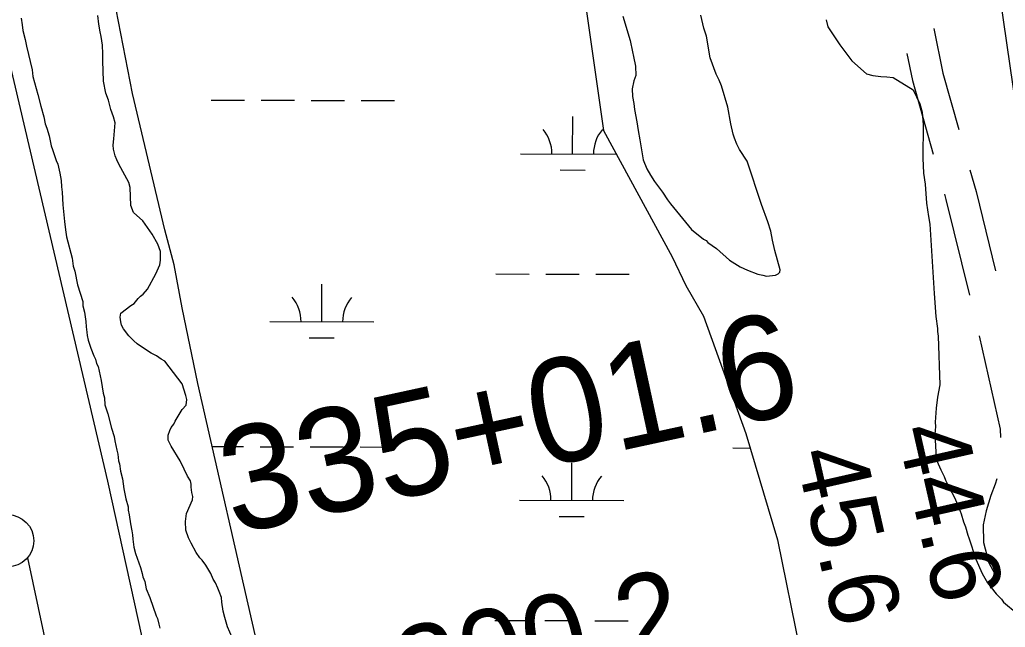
# Model space of a CAD drawing. Extents: x 3161665 to 3199565, y 885729 to 911164.
# Drawn here: x 3175026 to 3175972, y 895397 to 895980 of the extents above; entities that cross this region are included whole.
import ezdxf

# ---------------------------------------------------------------- set-up
doc = ezdxf.new("R2010")
doc.units = 0
for name, color, linetype in [('V-LEVE-TOET', 7, 'Continuous'), ('V-RIVR-RANG', 7, 'Continuous'), ('V-RIVR-RANG-IDEN', 7, 'Continuous'), ('V-ROAD-CNTR', 7, 'Continuous'), ('V-SITE-VEGE', 7, 'Continuous'), ('V-SURV-IDEN', 7, 'Continuous'), ('V-SURV-LINE', 7, 'Continuous'), ('V-TOPO-MINR', 7, 'Continuous'), ('V-TOPO-SHOR', 7, 'Continuous'), ('V-WETL-SWMP', 7, 'Continuous')]:
    doc.layers.add(name, color=color, linetype=linetype)

msp = doc.modelspace()

# ---------------------------------------------------------------- linework, layer by layer
at = {"layer": 'V-LEVE-TOET'}
msp.add_lwpolyline([(3174566.85, 897865.68), (3174635.83, 897583.71), (3174711.7, 897283.5), (3174795.82, 896920.93), (3174863.72, 896619.04), (3174934.5, 896318.62), (3175016.53, 895935.58), (3175109.93, 895536.94), (3175193.43, 895157.19), (3175269.57, 894793.2), (3175363, 894393.76), (3175446.73, 894021.24), (3175510.4, 893698.81), (3175596.82, 893326.15), (3175626.84, 893204.92), (3175671.16, 893055.89), (3175732.85, 892857.2), (3175831.28, 892583.94), (3175876.32, 892462.54)], dxfattribs=at)
at = {"layer": 'V-ROAD-CNTR'}
for points in [[(3175903.63, 895971.34), (3175912.46, 895928.49), (3175927.63, 895874.33)], [(3175877.9, 895947.57), (3175883.29, 895921.41), (3175903.06, 895850.84)], [(3175938.42, 895835.81), (3175944.25, 895814.99), (3175963, 895738.89)], [(3175913.85, 895812.32), (3175915.24, 895807.35), (3175937.93, 895715.27)], [(3175947.22, 895676.37), (3175967.48, 895586.71), (3175967.68, 895578.63)], [(3175964.21, 895539.05), (3175962.62, 895534.06), (3175958.57, 895523.06), (3175953.84, 895508.26), (3175951.11, 895494.99), (3175951.25, 895477.96), (3175956.5, 895458.26), (3175964.51, 895443.8)]]:
    msp.add_lwpolyline(points, dxfattribs=at)
at = {"layer": 'V-SITE-VEGE'}
for points in [[(3175139.39, 895712.06), (3175141.55, 895714.41), (3175144.18, 895716.32), (3175148.5, 895721.02), (3175156.45, 895735.8), (3175160.15, 895744.53), (3175160.86, 895749.08), (3175160.97, 895757.21), (3175158.41, 895764.32), (3175153.04, 895774.03), (3175143.93, 895786.74), (3175135.01, 895794.94), (3175132.47, 895801.6), (3175131.75, 895818.73), (3175130.64, 895823.65), (3175120.87, 895841.3), (3175118.9, 895845.28), (3175117.37, 895849.28), (3175115.76, 895855.53), (3175115.59, 895859.58), (3175116.24, 895865.48), (3175117.4, 895880.88), (3175115.8, 895886.68), (3175113.25, 895893.8), (3175111.07, 895902.73), (3175108.53, 895909.4), (3175106.23, 895921.04), (3175105.42, 895940.42), (3175105.58, 895947.2), (3175105.24, 895955.31), (3175103.98, 895963.83), (3175102.89, 895968.3), (3175101.69, 895975.47), (3175100.88, 895984.02)], [(3175605.14, 895983.45), (3175612, 895959.81), (3175614.26, 895949.07), (3175615.35, 895944.6), (3175617.1, 895935.19), (3175617.48, 895926.18), (3175615.44, 895921.13), (3175613.96, 895913.39), (3175614.26, 895906.18), (3175615.44, 895899.46), (3175616.14, 895893.62), (3175618.43, 895881.98), (3175619.7, 895873.45), (3175621.43, 895864.5), (3175624.49, 895845.22), (3175628.01, 895836.79), (3175631.43, 895830.61), (3175635.3, 895824.45), (3175642.94, 895814.39), (3175647.77, 895806.92), (3175650.65, 895802.98), (3175671.09, 895778.55), (3175682.32, 895769.09), (3175685.08, 895767.86), (3175686.51, 895766.11), (3175694.88, 895760.14), (3175707.54, 895748.94), (3175717.74, 895742.59), (3175724.65, 895739.27), (3175734.74, 895735.63), (3175739.3, 895734.47), (3175742.94, 895733.72), (3175751.49, 895734.53), (3175754.13, 895736), (3175755.88, 895737.42), (3175756.24, 895739.7), (3175750.93, 895758.43), (3175748.72, 895768.27), (3175747, 895776.78), (3175744.37, 895785.7), (3175738.24, 895802.59), (3175724.32, 895843.99), (3175717.06, 895855.43), (3175714.6, 895860.29), (3175712.1, 895866.05), (3175711.03, 895870.07), (3175708.81, 895879.91), (3175705.88, 895896.04), (3175699.6, 895916.54), (3175697.57, 895921.87), (3175694.62, 895927.62), (3175689, 895943.18), (3175685.4, 895964.25), (3175682.83, 895971.81), (3175680.05, 895984.34)], [(3175800.32, 895979.91), (3175801.95, 895973.21), (3175813.52, 895955.64), (3175825, 895940.32), (3175839.07, 895927.82), (3175845.01, 895926.26), (3175852.72, 895925.23), (3175858.6, 895925.03), (3175864.5, 895924.37), (3175883.96, 895912.55), (3175890.38, 895899.28), (3175892.53, 895891.24), (3175893.49, 895879.09), (3175893.03, 895847.02), (3175893.63, 895832.6), (3175895.44, 895821.84), (3175896.65, 895803.83), (3175898.55, 895790.82), (3175899.76, 895783.65), (3175903.91, 895717.01), (3175905.74, 895694.96), (3175907.13, 895683.29), (3175907.25, 895680.58), (3175907.89, 895676.09), (3175909.41, 895629.21), (3175907.19, 895617.38), (3175905.83, 895606.94), (3175905.04, 895593.36), (3175905.21, 895589.3), (3175904.63, 895581.6)], [(3175229.81, 895386.75), (3175225.32, 895396.95), (3175222.69, 895405.87), (3175221.07, 895412.12), (3175219.81, 895420.64), (3175219.62, 895425.15), (3175217.12, 895430.91), (3175216.08, 895434.03), (3175213.6, 895439.34), (3175211.65, 895442.87), (3175209.17, 895448.19), (3175204.32, 895456.11), (3175200.96, 895460.93), (3175198.61, 895463.09), (3175195.23, 895468.37), (3175190.35, 895477.19), (3175187.86, 895482.5), (3175185.31, 895489.62), (3175184.95, 895498.18), (3175185.98, 895505.9), (3175191.75, 895518.78), (3175192.07, 895521.96), (3175191, 895525.97), (3175190.34, 895530.91), (3175190.21, 895534.07), (3175189.63, 895537.2), (3175186.73, 895541.59), (3175183.75, 895548.24), (3175179.8, 895556.2), (3175171.08, 895570.28), (3175168.13, 895576.03), (3175168.38, 895581), (3175169.99, 895585.59), (3175171.23, 895588.35), (3175173.8, 895591.62), (3175175.04, 895594.37), (3175181.79, 895605.49), (3175185.68, 895609.72), (3175186.35, 895615.17), (3175185.28, 895619.18), (3175181.65, 895630.32), (3175164.93, 895652.19), (3175161.7, 895653.86), (3175157.05, 895657.27), (3175151.97, 895659.77), (3175146.41, 895663.15), (3175138.51, 895668.68), (3175135.22, 895671.7), (3175130.5, 895676.47), (3175125.26, 895683.02), (3175123.31, 895686.55), (3175122.73, 895689.69), (3175122.09, 895694.18), (3175122.82, 895698.27), (3175132.45, 895705.45), (3175135.53, 895707.38), (3175139.39, 895712.06)], [(3175904.63, 895581.6), (3175906.01, 895559.54), (3175906.6, 895556.41), (3175910.58, 895547.54), (3175913.55, 895541.35), (3175915.05, 895537.8), (3175918.51, 895530.72), (3175923.9, 895520.57), (3175928.94, 895508.14), (3175929.95, 895505.47), (3175932.08, 895497.89), (3175934.09, 895493), (3175936.23, 895484.97), (3175937.25, 895482.3), (3175943.98, 895461.82), (3175949.97, 895448.08), (3175955.31, 895439.27), (3175963.42, 895428.78), (3175968.61, 895423.58), (3175970.54, 895420.5), (3175983.63, 895409.76)]]:
    msp.add_lwpolyline(points, dxfattribs=at)
at = {"layer": 'V-SURV-LINE'}
msp.add_lwpolyline([(3175033.05, 895463.17), (3175421.29, 893644.8)], dxfattribs=at)
msp.add_circle((3175014.21, 895479.58), 25, dxfattribs=at)
at = {"layer": 'V-TOPO-MINR'}
msp.add_lwpolyline([(3175928.77, 896267.03), (3176033.29, 895545.25)], dxfattribs=at)
at = {"layer": 'V-TOPO-SHOR'}
for points in [[(3175026.95, 895981.36), (3175028.12, 895975.09), (3175028.8, 895969.7), (3175030.98, 895960.77), (3175032.15, 895954.49), (3175037.62, 895931.7), (3175038.33, 895925.41), (3175043.13, 895908), (3175045.85, 895896.83), (3175048.99, 895886.58), (3175050.18, 895879.86), (3175051.7, 895875.86), (3175053.83, 895868.28)], [(3175186.35, 895615.17), (3175185.28, 895619.18), (3175181.65, 895630.32), (3175164.93, 895652.19), (3175161.7, 895653.86), (3175157.04, 895657.27), (3175151.97, 895659.77), (3175146.41, 895663.15), (3175138.51, 895668.68), (3175135.22, 895671.7), (3175130.5, 895676.47), (3175125.26, 895683.02), (3175123.31, 895686.55), (3175122.73, 895689.69), (3175122.09, 895694.18), (3175122.82, 895698.27), (3175132.45, 895705.45), (3175135.53, 895707.38), (3175139.39, 895712.06), (3175141.55, 895714.41), (3175144.18, 895716.32), (3175148.5, 895721.02), (3175156.45, 895735.8), (3175160.15, 895744.53), (3175160.86, 895749.08), (3175160.97, 895757.21), (3175158.41, 895764.32), (3175153.04, 895774.03), (3175143.93, 895786.74), (3175135.01, 895794.94), (3175132.47, 895801.6), (3175131.75, 895818.73), (3175130.64, 895823.65), (3175120.87, 895841.3), (3175118.9, 895845.28), (3175117.37, 895849.28), (3175115.76, 895855.53), (3175115.59, 895859.58), (3175116.24, 895865.48), (3175117.4, 895880.88), (3175115.8, 895886.68), (3175113.25, 895893.8), (3175111.07, 895902.73), (3175108.53, 895909.4), (3175106.23, 895921.04), (3175105.42, 895940.42), (3175105.58, 895947.2), (3175105.24, 895955.31), (3175103.98, 895963.83), (3175102.89, 895968.3), (3175101.69, 895975.47), (3175100.88, 895984.02)], [(3175053.83, 895868.28), (3175056.03, 895858.89), (3175057.08, 895855.32), (3175060.69, 895844.64), (3175062.19, 895841.09), (3175064.35, 895832.6), (3175065.56, 895825.43), (3175065.8, 895819.57), (3175066.48, 895814.18), (3175066.99, 895802.01), (3175068.56, 895786.28), (3175069.8, 895778.2), (3175070.54, 895771.46), (3175075.91, 895750.93), (3175077.14, 895743.3), (3175078.7, 895738.4), (3175081.05, 895725.41), (3175086.24, 895709.37), (3175086.41, 895705.32), (3175088.02, 895699.07), (3175089.3, 895690.09), (3175089.51, 895685.13), (3175090.19, 895679.74), (3175090.32, 895676.59), (3175091.41, 895672.12), (3175093.99, 895664.55), (3175097.01, 895657.01), (3175098.5, 895653.91), (3175099.57, 895649.89), (3175101.05, 895646.79), (3175103.87, 895633.37), (3175105.74, 895621.26), (3175107.28, 895616.81), (3175107.56, 895610.05), (3175110.18, 895601.58), (3175113.92, 895587.74), (3175116.51, 895579.73), (3175117.13, 895575.69), (3175118.86, 895566.73), (3175119.94, 895562.72), (3175120.65, 895556.42), (3175121.69, 895553.31), (3175122.42, 895546.57), (3175124.54, 895538.98), (3175125.85, 895529.56), (3175127.61, 895519.7), (3175129.74, 895512.11), (3175129.87, 895508.96), (3175130.96, 895504.49), (3175132.22, 895495.97), (3175133.41, 895489.24), (3175134.03, 895485.21), (3175134.2, 895481.15), (3175135.42, 895473.53), (3175137.04, 895467.28), (3175141.66, 895453.93), (3175143.26, 895448.13), (3175143.84, 895444.99), (3175145.84, 895440.56), (3175147.04, 895433.39), (3175150.55, 895424.96), (3175156.7, 895407.61), (3175158.17, 895404.96), (3175159.3, 895399.59), (3175160.37, 895395.57)], [(3175229.81, 895386.75), (3175225.32, 895396.95), (3175222.69, 895405.87), (3175221.07, 895412.12), (3175219.81, 895420.64), (3175219.62, 895425.15), (3175217.12, 895430.91), (3175216.08, 895434.03), (3175213.6, 895439.34), (3175211.65, 895442.87), (3175209.17, 895448.19), (3175204.32, 895456.11), (3175200.96, 895460.93), (3175198.61, 895463.09), (3175195.23, 895468.37), (3175190.35, 895477.19), (3175187.86, 895482.5), (3175185.31, 895489.62), (3175184.95, 895498.18), (3175185.98, 895505.9), (3175191.76, 895518.78), (3175192.07, 895521.96), (3175191, 895525.97), (3175190.34, 895530.91), (3175190.21, 895534.07), (3175189.63, 895537.2), (3175186.73, 895541.59), (3175183.75, 895548.24), (3175179.8, 895556.2), (3175171.08, 895570.28), (3175168.13, 895576.03), (3175168.38, 895581), (3175169.99, 895585.59), (3175171.23, 895588.35), (3175173.8, 895591.62), (3175175.04, 895594.37), (3175181.79, 895605.49), (3175185.68, 895609.72), (3175186.35, 895615.17)]]:
    msp.add_lwpolyline(points, dxfattribs=at)
at = {"layer": 'V-WETL-SWMP'}
for p, q in [((3175544.67, 896167.43), (3175586.51, 895873.63)), ((3175133.95, 895908.9), (3175114.7, 896008.87)), ((3175165.03, 895778.18), (3175133.95, 895908.9)), ((3175209.62, 895902.73), (3175241.62, 895902.64)), ((3175257.62, 895902.6), (3175289.62, 895902.51)), ((3175305.62, 895902.47), (3175337.62, 895902.38)), ((3175353.62, 895902.33), (3175385.62, 895902.25)), ((3175556.79, 895851.03), (3175556.89, 895887.03)), ((3175586.51, 895873.63), (3175652.28, 895752.07)), ((3175506.79, 895851.17), (3175598.8, 895850.92)), ((3175544.75, 895835.63), (3175568.75, 895835.57)), ((3175174.07, 895744.39), (3175165.03, 895778.18)), ((3175652.28, 895752.07), (3175665.58, 895724.81)), ((3175181.85, 895703.31), (3175174.07, 895744.39)), ((3175483.06, 895735.8), (3175515.06, 895735.71)), ((3175531.06, 895735.67), (3175563.06, 895735.58)), ((3175579.06, 895735.54), (3175611.06, 895735.45)), ((3175315.87, 895689.83), (3175315.97, 895725.83)), ((3175665.58, 895724.81), (3175682.49, 895695.36)), ((3175196.82, 895630.7), (3175181.85, 895703.31)), ((3175682.49, 895695.36), (3175723.27, 895582.68)), ((3175265.87, 895689.97), (3175365.87, 895689.7)), ((3175303.83, 895674.44), (3175327.83, 895674.37)), ((3175253.56, 895382.12), (3175196.82, 895630.7)), ((3175723.27, 895582.68), (3175753.42, 895480.52)), ((3175210.66, 895570.05), (3175240.7, 895569.97)), ((3175256.7, 895569.93), (3175288.7, 895569.84)), ((3175304.7, 895569.79), (3175336.7, 895569.71)), ((3175352.7, 895569.66), (3175384.7, 895569.57)), ((3175710.6, 895568.67), (3175727.41, 895568.63)), ((3175555.87, 895518.36), (3175555.97, 895554.36)), ((3175505.87, 895518.5), (3175605.87, 895518.22)), ((3175543.83, 895502.96), (3175567.83, 895502.89)), ((3175753.42, 895480.52), (3175805.29, 895225.31)), ((3175482.14, 895403.13), (3175514.14, 895403.04)), ((3175530.14, 895403), (3175562.14, 895402.91)), ((3175578.14, 895402.86), (3175610.14, 895402.77))]:
    msp.add_line(p, q, dxfattribs=at)
for centre, start, end in [((3175501.55, 895851.66), 359.06985, 40.6135), ((3175612.03, 895851.35), 139.06984, 180.6135), ((3175260.63, 895690.46), 359.06985, 40.6135), ((3175371.12, 895690.16), 139.06984, 180.6135), ((3175500.63, 895518.98), 359.06985, 40.6135), ((3175611.12, 895518.68), 139.06984, 180.6135)]:
    msp.add_arc(centre, 35.25, start, end, dxfattribs=at)

# ---------------------------------------------------------------- texts
at = {"layer": 'V-RIVR-RANG'}
for s, p in [('44.6', (3175867.78, 895585.95)), ('45.6', (3175770.32, 895563.56))]:
    msp.add_text(s, height=67, rotation=282.79833, dxfattribs=at).set_placement(p)
at = {"layer": 'V-RIVR-RANG-IDEN'}
msp.add_text('R-300.2', height=83, rotation=12.93818, dxfattribs=at).set_placement((3175284.12, 895285.25))
at = {"layer": 'V-SURV-IDEN'}
msp.add_text('335+01.6', height=100, rotation=12.22111, dxfattribs=at).set_placement((3175230.83, 895485.32))

doc.saveas('drawing.dxf')
